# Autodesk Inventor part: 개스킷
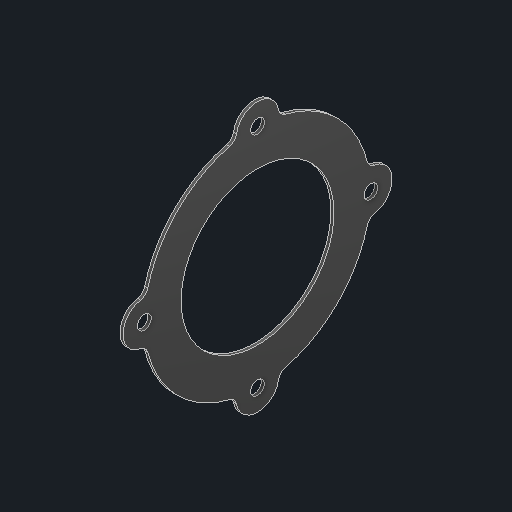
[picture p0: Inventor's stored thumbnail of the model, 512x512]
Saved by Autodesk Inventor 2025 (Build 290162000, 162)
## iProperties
Created: 2025-08
Part Number: 개스킷
Material: 황동, 연질 노란색
Document SubType Name: Modeling
Designer: infra14
Density: 8.47 g/cm^3
Appearance: 기본값
Author: jhkim
Sending System: Autodesk Inventor 2026
Preprocessor: ST-DEVELOPER v20.1
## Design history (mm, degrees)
feature "솔리드2"
node "솔리드1"
